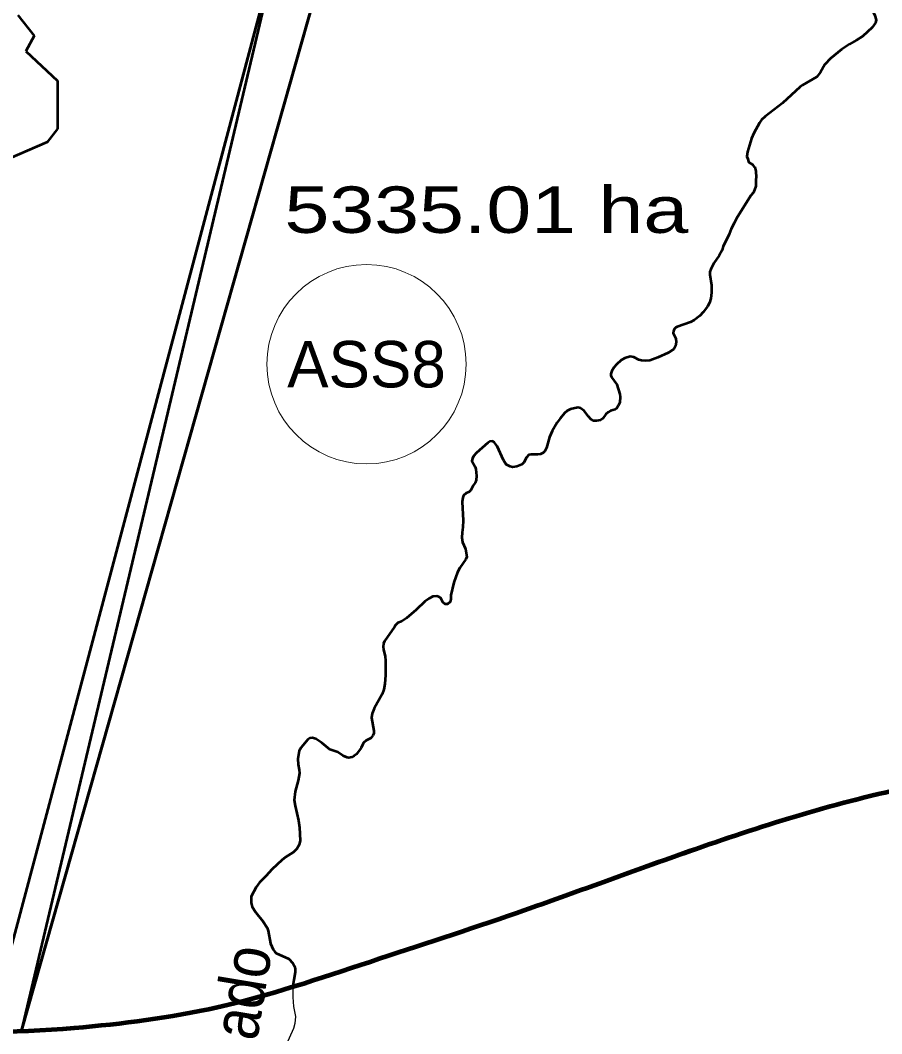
# Model space of a CAD drawing. Extents: x -1643653 to 4543381, y 1624270 to 13878484.
# Drawn here: x 618603 to 627885, y 8953910 to 8964825 of the extents above; entities that cross this region are included whole.
import ezdxf
from ezdxf.enums import TextEntityAlignment as Align

# ---------------------------------------------------------------- set-up
doc = ezdxf.new("R2010")
doc.units = 0
doc.header["$LTSCALE"] = 200
doc.linetypes.add('MEDIUM_DASHED', pattern=[4.5, 3, -1.5])
for name, color, linetype, lineweight in [('1', 7, 'Continuous', 13), ('24', 7, 'Continuous', 25), ('26', 7, 'Continuous', 106), ('27', 7, 'Continuous', 53), ('28', 7, 'Continuous', 53), ('29', 7, 'Continuous', 13), ('45', 7, 'Continuous', 13)]:
    doc.layers.add(name, color=color, linetype=linetype, lineweight=lineweight)
doc.layers.add('49', color=7, linetype='Continuous')
doc.layers.add('63', color=7, linetype='Continuous')

msp = doc.modelspace()

# ---------------------------------------------------------------- linework, layer by layer
at = {"layer": '1', "lineweight": 25}
msp.add_spline([(814781, 9009175.5), (814787.2, 9009173.4), (814796.9, 9009173.4), (814799.4, 9009172.4), (814805.1, 9009174.5), (814805.6, 9009176.5), (814811.7, 9009179.5), (814811.7, 9009179.5), (814801.5, 9009181), (814790.7, 9009181.5), (814784.1, 9009183.1), (814777.4, 9009185.1), (814778.4, 9009175.5)], degree=3, dxfattribs=at)
at = {"layer": '24'}
for points in [[(627864.4, 8965796.7), (627870.8, 8965773.8), (627867.2, 8965732.7), (627839, 8965684.6), (627827.1, 8965654.5), (627811.8, 8965541.3), (627811.5, 8965505.3), (627817.4, 8965449.2), (627838.1, 8965372.1), (627841, 8965321), (627826.7, 8965271.9), (627798.1, 8965236.8), (627783.4, 8965207.8), (627766.8, 8965123.6), (627733.2, 8965082.5), (627726.4, 8965067.5), (627723.3, 8965046.4), (627728.3, 8965015.4), (627739.7, 8964986.4), (627792.5, 8964916.3), (627811.7, 8964876.3), (627823.6, 8964830.2), (627816, 8964796.2)], [(627816, 8964796.2), (627816, 8964796.2), (627780.2, 8964746.1), (627680.5, 8964655.8), (627612, 8964609.6), (627536.8, 8964566.4), (627449.5, 8964509.2), (627333.7, 8964414.8), (627272.4, 8964348.6), (627225, 8964267.4), (627185.5, 8964217.3), (627032.1, 8964127.9), (627004.7, 8964107.8), (626815.8, 8963934.3), (626629.8, 8963789.7), (626590.1, 8963751.6), (626566.7, 8963720.5), (626506, 8963608.3), (626480.1, 8963551.1), (626439.9, 8963406.8), (626430.6, 8963358.8), (626441.2, 8963331.8), (626448.8, 8963299.7), (626457.1, 8963293.7), (626491.3, 8963272.5), (626505.7, 8963251), (626515.9, 8963242.8), (626529.7, 8963201.7), (626531.3, 8963131.3), (626529.2, 8963109.8), (626529.5, 8963038.6), (626501.7, 8962971.9), (626473.9, 8962938.6), (626318.3, 8962688.6), (626296, 8962638.6), (626262.7, 8962577.5), (626240.4, 8962522), (626212.7, 8962460.8), (626174.8, 8962393.8), (626164.1, 8962350.8), (626134.9, 8962291.6), (626076.5, 8962209.4), (626043, 8962145.2), (626033.4, 8962116.2), (626031, 8962086.1), (626050.8, 8961971), (626052.2, 8961893.9), (626043.5, 8961829.8), (626030, 8961782.7), (626007.6, 8961741.6), (625960.4, 8961681.4), (625923.5, 8961643.3), (625862.9, 8961595.1), (625822.7, 8961574), (625681.1, 8961524.7), (625666.2, 8961515.7), (625650, 8961497.6), (625640, 8961477.6), (625636.3, 8961455.5), (625664.5, 8961397.5), (625669.9, 8961359.4), (625663.1, 8961316.3), (625644, 8961283.3), (625582.5, 8961243.1), (625473.5, 8961191.8)], [(625473.5, 8961191.8), (625385.3, 8961162.7), (625335.4, 8961158.6), (625297, 8961160.5), (625268.2, 8961168.5), (625214.1, 8961198.5), (625173.4, 8961205.4), (625117.9, 8961186.3), (625078.9, 8961163.2), (625027.5, 8961119), (625000.9, 8961089), (624975.3, 8961048.8), (624966.1, 8961016.8), (624966.2, 8960999.8), (624973, 8960982.7), (625029.9, 8960900.7), (625064.6, 8960798.6), (625067, 8960768.6), (625061.1, 8960709.5), (625046, 8960671.4), (625027.5, 8960644.3), (625011.3, 8960634.2), (624961, 8960619.2), (624936.3, 8960606.1), (624912, 8960582), (624879.5, 8960536.9), (624854.3, 8960516.8), (624811.3, 8960509.7), (624784.5, 8960512.7), (624750.7, 8960527.7), (624725.6, 8960556.7), (624680, 8960618.7), (624640.1, 8960648.7), (624615.7, 8960653.7), (624577.3, 8960648.6), (624531.2, 8960635.5), (624496.8, 8960619.4)], [(624496.8, 8960619.4), (624466.5, 8960595.3), (624466.5, 8960595.3), (624418.2, 8960536.2), (624388.4, 8960493.1), (624334.1, 8960398.8), (624304.9, 8960334.7), (624271.6, 8960219.4), (624255.9, 8960184.4), (624237, 8960167.3), (624209.4, 8960152.2), (624177.8, 8960149.2), (624105.6, 8960150.1), (624084, 8960144), (624056.4, 8960117.9), (624029.7, 8960062.8), (624008.5, 8960040.7), (623952.6, 8960017.6), (623906.6, 8960011.5), (623879.7, 8960018.5), (623839.9, 8960041.5), (623809.1, 8960087.5), (623742.1, 8960236.6), (623708.6, 8960280.6), (623691, 8960291.6), (623663.5, 8960287.6), (623642.3, 8960274.5), (623518.1, 8960166.2), (623487.9, 8960132.1), (623473.9, 8960107), (623469.3, 8960080), (623503, 8960016.9), (623511.8, 8959991.9), (623518.8, 8959918.8), (623515.2, 8959871.7), (623503, 8959841.6), (623483.8, 8959814.6), (623458.3, 8959764.4), (623435.3, 8959743.4), (623405.8, 8959733.3), (623380.1, 8959708.2), (623370, 8959684.2), (623363, 8959639.1), (623374, 8959437.8), (623371.3, 8959365.7), (623362.7, 8959309.6), (623359.5, 8959254.5), (623367, 8959203.4), (623399.7, 8959131.4), (623414.8, 8959045.2), (623404.2, 8959022.2), (623338.3, 8958926.9), (623315, 8958880.8), (623272.9, 8958769.6), (623243.1, 8958633.3), (623241.6, 8958590.3), (623234, 8958561.2), (623207.1, 8958537.1), (623180.9, 8958538.1), (623154, 8958559.1), (623142.4, 8958588.1), (623129.2, 8958606.1), (623114.3, 8958616.1), (623091.3, 8958624.1), (623048.1, 8958618)], [(623048.1, 8958618), (623008.6, 8958598.9), (622961, 8958563.8), (622867, 8958474.5), (622765.3, 8958385.2), (622710.3, 8958350.1), (622672.6, 8958336), (622645.8, 8958310.9), (622635.8, 8958292.8), (622526.4, 8958139.4), (622516.5, 8958114.4), (622511.7, 8958078.3), (622515.3, 8958048.3), (622533.3, 8957971.2), (622537.7, 8957930.1), (622539.2, 8957771.9), (622532.6, 8957678.7), (622519.6, 8957617.6), (622503, 8957566.5), (622414.7, 8957413.1), (622392.8, 8957358), (622387.2, 8957313.9), (622413.1, 8957173.7), (622412, 8957144.7), (622401.3, 8957121.6), (622379.3, 8957091.6), (622329.5, 8957067.4), (622303.6, 8957046.4), (622292.3, 8957028.3), (622277.2, 8956988.2), (622224.7, 8956922.1), (622199.4, 8956902), (622173.6, 8956888.9), (622144.5, 8956882.9), (622124.1, 8956884.8), (622082.2, 8956903.8), (622023.4, 8956940.8)], [(622023.4, 8956940.8), (621940, 8956970.7), (621852.9, 8957044.7), (621852.9, 8957044.7), (621788.3, 8957084.6), (621747.1, 8957098.6), (621722, 8957094.5), (621699.9, 8957079.5), (621630.5, 8956993.2), (621609.1, 8956955.1), (621593, 8956869), (621597.7, 8956809.9), (621609.5, 8956752.8), (621610.3, 8956716.8), (621596.7, 8956635.6), (621564.2, 8956517.4), (621555.7, 8956425.2), (621563.4, 8956363.1), (621602.1, 8956205), (621612.3, 8956132.8), (621617.2, 8955989.6), (621609.4, 8955942.6), (621581.9, 8955900.4), (621546.5, 8955864.3), (621462.3, 8955810.1), (621421.6, 8955778), (621315.5, 8955681.7), (621248.5, 8955606.5), (621180.3, 8955539.2), (621144.2, 8955490.1), (621090.8, 8955387.9), (621089.6, 8955318.8), (621102.6, 8955276.7), (621141.2, 8955216.7), (621216.2, 8955123.7), (621263.9, 8955050.6), (621273.7, 8955018.6), (621298.4, 8954880.4), (621326.6, 8954818.3), (621344.8, 8954792.3), (621361.2, 8954778.3), (621494.9, 8954716.5), (621540.7, 8954668.5), (621556.5, 8954637.4), (621563.9, 8954607.4), (621564.5, 8954574.3), (621548.8, 8954491.2), (621540.9, 8954424.1), (621539.7, 8954301.9), (621548, 8954202.7), (621568.6, 8954096.6), (621562.7, 8954019.5), (621547, 8953964.4), (621433.8, 8953717.8)]]:
    msp.add_lwpolyline(points, dxfattribs=at)
at = {"layer": '26'}
msp.add_spline([(645710.9, 8949471.4), (644721.9, 8950215.5), (643631.5, 8951123.7), (642665.6, 8952010.9), (642072.6, 8952588.9), (640582.3, 8953977.6), (638005.5, 8955508.7), (636255.8, 8956201.4), (634307.9, 8956672.6), (632583.3, 8956799.8), (628516.3, 8956628.1), (626161.4, 8955993.9), (623953.8, 8955209.7), (622371.6, 8954682.1), (620725.9, 8954192.9), (619183.7, 8953970.3), (617209.7, 8953965.7), (615658.4, 8954379), (614681.6, 8955057.1), (613704.6, 8955684.2), (612906.2, 8956374.2), (612068.3, 8956835.4), (609416.9, 8956401.3), (608625.2, 8956035.7), (607870.9, 8955517.4), (607396.1, 8954883.6), (607164, 8954388.6), (606950.6, 8954069.9)], degree=3, dxfattribs=at)
at = {"layer": '27'}
msp.add_line((618614.3, 8953943), (622031.1, 8965989.3), dxfattribs=at)
for points in [[(621430.6, 8965386.2), (622031.1, 8965989.3), (618614.3, 8953943), (618257.6, 8953925.9)], [(627864.4, 8965796.7), (627870.8, 8965773.8), (627867.2, 8965732.7), (627839, 8965684.6), (627827.1, 8965654.5), (627811.8, 8965541.3), (627811.5, 8965505.3), (627817.4, 8965449.2), (627838.1, 8965372.1), (627841, 8965321), (627826.7, 8965271.9), (627798.1, 8965236.8), (627783.4, 8965207.8), (627766.8, 8965123.6), (627733.2, 8965082.5), (627726.4, 8965067.5), (627723.3, 8965046.4), (627728.3, 8965015.4), (627739.7, 8964986.4), (627792.5, 8964916.3), (627811.7, 8964876.3), (627823.6, 8964830.2), (627816, 8964796.2)], [(627864.4, 8965796.7), (627870.8, 8965773.8), (627867.2, 8965732.7), (627839, 8965684.6), (627827.1, 8965654.5), (627811.8, 8965541.3), (627811.5, 8965505.3), (627817.4, 8965449.2), (627838.1, 8965372.1), (627841, 8965321), (627826.7, 8965271.9), (627798.1, 8965236.8), (627783.4, 8965207.8), (627766.8, 8965123.6), (627733.2, 8965082.5), (627726.4, 8965067.5), (627723.3, 8965046.4), (627728.3, 8965015.4), (627739.7, 8964986.4), (627792.5, 8964916.3), (627811.7, 8964876.3), (627823.6, 8964830.2), (627816, 8964796.2)], [(627816, 8964796.2), (627816, 8964796.2), (627780.2, 8964746.1), (627680.5, 8964655.8), (627612, 8964609.6), (627536.8, 8964566.4), (627449.5, 8964509.2), (627333.7, 8964414.8), (627272.4, 8964348.6), (627225, 8964267.4), (627185.5, 8964217.3), (627032.1, 8964127.9), (627004.7, 8964107.8), (626815.8, 8963934.3), (626629.8, 8963789.7), (626590.1, 8963751.6), (626566.7, 8963720.5), (626506, 8963608.3), (626480.1, 8963551.1), (626439.9, 8963406.8), (626430.6, 8963358.8), (626441.2, 8963331.8), (626448.8, 8963299.7), (626457.1, 8963293.7), (626491.3, 8963272.5), (626505.7, 8963251), (626515.9, 8963242.8), (626529.7, 8963201.7), (626531.3, 8963131.3), (626529.2, 8963109.8), (626529.5, 8963038.6), (626501.7, 8962971.9), (626473.9, 8962938.6), (626318.3, 8962688.6), (626296, 8962638.6), (626262.7, 8962577.5), (626240.4, 8962522), (626212.7, 8962460.8), (626174.8, 8962393.8), (626164.1, 8962350.8), (626134.9, 8962291.6), (626076.5, 8962209.4), (626043, 8962145.2), (626033.4, 8962116.2), (626031, 8962086.1), (626050.8, 8961971), (626052.2, 8961893.9), (626043.5, 8961829.8), (626030, 8961782.7), (626007.6, 8961741.6), (625960.4, 8961681.4), (625923.5, 8961643.3), (625862.9, 8961595.1), (625822.7, 8961574), (625681.1, 8961524.7), (625666.2, 8961515.7), (625650, 8961497.6), (625640, 8961477.6), (625636.3, 8961455.5), (625664.5, 8961397.5), (625669.9, 8961359.4), (625663.1, 8961316.3), (625644, 8961283.3), (625582.5, 8961243.1), (625473.5, 8961191.8)], [(627816, 8964796.2), (627816, 8964796.2), (627780.2, 8964746.1), (627680.5, 8964655.8), (627612, 8964609.6), (627536.8, 8964566.4), (627449.5, 8964509.2), (627333.7, 8964414.8), (627272.4, 8964348.6), (627225, 8964267.4), (627185.5, 8964217.3), (627032.1, 8964127.9), (627004.7, 8964107.8), (626815.8, 8963934.3), (626629.8, 8963789.7), (626590.1, 8963751.6), (626566.7, 8963720.5), (626506, 8963608.3), (626480.1, 8963551.1), (626439.9, 8963406.8), (626430.6, 8963358.8), (626441.2, 8963331.8), (626448.8, 8963299.7), (626457.1, 8963293.7), (626491.3, 8963272.5), (626505.7, 8963251), (626515.9, 8963242.8), (626529.7, 8963201.7), (626531.3, 8963131.3), (626529.2, 8963109.8), (626529.5, 8963038.6), (626501.7, 8962971.9), (626473.9, 8962938.6), (626318.3, 8962688.6), (626296, 8962638.6), (626262.7, 8962577.5), (626240.4, 8962522), (626212.7, 8962460.8), (626174.8, 8962393.8), (626164.1, 8962350.8), (626134.9, 8962291.6), (626076.5, 8962209.4), (626043, 8962145.2), (626033.4, 8962116.2), (626031, 8962086.1), (626050.8, 8961971), (626052.2, 8961893.9), (626043.5, 8961829.8), (626030, 8961782.7), (626007.6, 8961741.6), (625960.4, 8961681.4), (625923.5, 8961643.3), (625862.9, 8961595.1), (625822.7, 8961574), (625681.1, 8961524.7), (625666.2, 8961515.7), (625650, 8961497.6), (625640, 8961477.6), (625636.3, 8961455.5), (625664.5, 8961397.5), (625669.9, 8961359.4), (625663.1, 8961316.3), (625644, 8961283.3), (625582.5, 8961243.1), (625473.5, 8961191.8)], [(625473.5, 8961191.8), (625385.3, 8961162.7), (625335.4, 8961158.6), (625297, 8961160.5), (625268.2, 8961168.5), (625214.1, 8961198.5), (625173.4, 8961205.4), (625117.9, 8961186.3), (625078.9, 8961163.2), (625027.5, 8961119), (625000.9, 8961089), (624975.3, 8961048.8), (624966.1, 8961016.8), (624966.2, 8960999.8), (624973, 8960982.7), (625029.9, 8960900.7), (625064.6, 8960798.6), (625067, 8960768.6), (625061.1, 8960709.5), (625046, 8960671.4), (625027.5, 8960644.3), (625011.3, 8960634.2), (624961, 8960619.2), (624936.3, 8960606.1), (624912, 8960582), (624879.5, 8960536.9), (624854.3, 8960516.8), (624811.3, 8960509.7), (624784.5, 8960512.7), (624750.7, 8960527.7), (624725.6, 8960556.7), (624680, 8960618.7), (624640.1, 8960648.7), (624615.7, 8960653.7), (624577.3, 8960648.6), (624531.2, 8960635.5), (624496.8, 8960619.4)], [(625473.5, 8961191.8), (625385.3, 8961162.7), (625335.4, 8961158.6), (625297, 8961160.5), (625268.2, 8961168.5), (625214.1, 8961198.5), (625173.4, 8961205.4), (625117.9, 8961186.3), (625078.9, 8961163.2), (625027.5, 8961119), (625000.9, 8961089), (624975.3, 8961048.8), (624966.1, 8961016.8), (624966.2, 8960999.8), (624973, 8960982.7), (625029.9, 8960900.7), (625064.6, 8960798.6), (625067, 8960768.6), (625061.1, 8960709.5), (625046, 8960671.4), (625027.5, 8960644.3), (625011.3, 8960634.2), (624961, 8960619.2), (624936.3, 8960606.1), (624912, 8960582), (624879.5, 8960536.9), (624854.3, 8960516.8), (624811.3, 8960509.7), (624784.5, 8960512.7), (624750.7, 8960527.7), (624725.6, 8960556.7), (624680, 8960618.7), (624640.1, 8960648.7), (624615.7, 8960653.7), (624577.3, 8960648.6), (624531.2, 8960635.5), (624496.8, 8960619.4)], [(624496.8, 8960619.4), (624466.5, 8960595.3), (624466.5, 8960595.3), (624418.2, 8960536.2), (624388.4, 8960493.1), (624334.1, 8960398.8), (624304.9, 8960334.7), (624271.6, 8960219.4), (624255.9, 8960184.4), (624237, 8960167.3), (624209.4, 8960152.2), (624177.8, 8960149.2), (624105.6, 8960150.1), (624084, 8960144), (624056.4, 8960117.9), (624029.7, 8960062.8), (624008.5, 8960040.7), (623952.6, 8960017.6), (623906.6, 8960011.5), (623879.7, 8960018.5), (623839.9, 8960041.5), (623809.1, 8960087.5), (623742.1, 8960236.6), (623708.6, 8960280.6), (623691, 8960291.6), (623663.5, 8960287.6), (623642.3, 8960274.5), (623518.1, 8960166.2), (623487.9, 8960132.1), (623473.9, 8960107), (623469.3, 8960080), (623503, 8960016.9), (623511.8, 8959991.9), (623518.8, 8959918.8), (623515.2, 8959871.7), (623503, 8959841.6), (623483.8, 8959814.6), (623458.3, 8959764.4), (623435.3, 8959743.4), (623405.8, 8959733.3), (623380.1, 8959708.2), (623370, 8959684.2), (623363, 8959639.1), (623374, 8959437.8), (623371.3, 8959365.7), (623362.7, 8959309.6), (623359.5, 8959254.5), (623367, 8959203.4), (623399.7, 8959131.4), (623414.8, 8959045.2), (623404.2, 8959022.2), (623338.3, 8958926.9), (623315, 8958880.8), (623272.9, 8958769.6), (623243.1, 8958633.3), (623241.6, 8958590.3), (623234, 8958561.2), (623207.1, 8958537.1), (623180.9, 8958538.1), (623154, 8958559.1), (623142.4, 8958588.1), (623129.2, 8958606.1), (623114.3, 8958616.1), (623091.3, 8958624.1), (623048.1, 8958618)], [(624496.8, 8960619.4), (624466.5, 8960595.3), (624466.5, 8960595.3), (624418.2, 8960536.2), (624388.4, 8960493.1), (624334.1, 8960398.8), (624304.9, 8960334.7), (624271.6, 8960219.4), (624255.9, 8960184.4), (624237, 8960167.3), (624209.4, 8960152.2), (624177.8, 8960149.2), (624105.6, 8960150.1), (624084, 8960144), (624056.4, 8960117.9), (624029.7, 8960062.8), (624008.5, 8960040.7), (623952.6, 8960017.6), (623906.6, 8960011.5), (623879.7, 8960018.5), (623839.9, 8960041.5), (623809.1, 8960087.5), (623742.1, 8960236.6), (623708.6, 8960280.6), (623691, 8960291.6), (623663.5, 8960287.6), (623642.3, 8960274.5), (623518.1, 8960166.2), (623487.9, 8960132.1), (623473.9, 8960107), (623469.3, 8960080), (623503, 8960016.9), (623511.8, 8959991.9), (623518.8, 8959918.8), (623515.2, 8959871.7), (623503, 8959841.6), (623483.8, 8959814.6), (623458.3, 8959764.4), (623435.3, 8959743.4), (623405.8, 8959733.3), (623380.1, 8959708.2), (623370, 8959684.2), (623363, 8959639.1), (623374, 8959437.8), (623371.3, 8959365.7), (623362.7, 8959309.6), (623359.5, 8959254.5), (623367, 8959203.4), (623399.7, 8959131.4), (623414.8, 8959045.2), (623404.2, 8959022.2), (623338.3, 8958926.9), (623315, 8958880.8), (623272.9, 8958769.6), (623243.1, 8958633.3), (623241.6, 8958590.3), (623234, 8958561.2), (623207.1, 8958537.1), (623180.9, 8958538.1), (623154, 8958559.1), (623142.4, 8958588.1), (623129.2, 8958606.1), (623114.3, 8958616.1), (623091.3, 8958624.1), (623048.1, 8958618)], [(623048.1, 8958618), (623008.6, 8958598.9), (622961, 8958563.8), (622867, 8958474.5), (622765.3, 8958385.2), (622710.3, 8958350.1), (622672.6, 8958336), (622645.8, 8958310.9), (622635.8, 8958292.8), (622526.4, 8958139.4), (622516.5, 8958114.4), (622511.7, 8958078.3), (622515.3, 8958048.3), (622533.3, 8957971.2), (622537.7, 8957930.1), (622539.2, 8957771.9), (622532.6, 8957678.7), (622519.6, 8957617.6), (622503, 8957566.5), (622414.7, 8957413.1), (622392.8, 8957358), (622387.2, 8957313.9), (622413.1, 8957173.7), (622412, 8957144.7), (622401.3, 8957121.6), (622379.3, 8957091.6), (622329.5, 8957067.4), (622303.6, 8957046.4), (622292.3, 8957028.3), (622277.2, 8956988.2), (622224.7, 8956922.1), (622199.4, 8956902), (622173.6, 8956888.9), (622144.5, 8956882.9), (622124.1, 8956884.8), (622082.2, 8956903.8), (622023.4, 8956940.8)], [(623048.1, 8958618), (623008.6, 8958598.9), (622961, 8958563.8), (622867, 8958474.5), (622765.3, 8958385.2), (622710.3, 8958350.1), (622672.6, 8958336), (622645.8, 8958310.9), (622635.8, 8958292.8), (622526.4, 8958139.4), (622516.5, 8958114.4), (622511.7, 8958078.3), (622515.3, 8958048.3), (622533.3, 8957971.2), (622537.7, 8957930.1), (622539.2, 8957771.9), (622532.6, 8957678.7), (622519.6, 8957617.6), (622503, 8957566.5), (622414.7, 8957413.1), (622392.8, 8957358), (622387.2, 8957313.9), (622413.1, 8957173.7), (622412, 8957144.7), (622401.3, 8957121.6), (622379.3, 8957091.6), (622329.5, 8957067.4), (622303.6, 8957046.4), (622292.3, 8957028.3), (622277.2, 8956988.2), (622224.7, 8956922.1), (622199.4, 8956902), (622173.6, 8956888.9), (622144.5, 8956882.9), (622124.1, 8956884.8), (622082.2, 8956903.8), (622023.4, 8956940.8)], [(622023.4, 8956940.8), (621940, 8956970.7), (621852.9, 8957044.7), (621852.9, 8957044.7), (621788.3, 8957084.6), (621747.1, 8957098.6), (621722, 8957094.5), (621699.9, 8957079.5), (621630.5, 8956993.2), (621609.1, 8956955.1), (621593, 8956869), (621597.7, 8956809.9), (621609.5, 8956752.8), (621610.3, 8956716.8), (621596.7, 8956635.6), (621564.2, 8956517.4), (621555.7, 8956425.2), (621563.4, 8956363.1), (621602.1, 8956205), (621612.3, 8956132.8), (621617.2, 8955989.6), (621609.4, 8955942.6), (621581.9, 8955900.4), (621546.5, 8955864.3), (621462.3, 8955810.1), (621421.6, 8955778), (621315.5, 8955681.7), (621248.5, 8955606.5), (621180.3, 8955539.2), (621144.2, 8955490.1), (621090.8, 8955387.9), (621089.6, 8955318.8), (621102.6, 8955276.7), (621141.2, 8955216.7), (621216.2, 8955123.7), (621263.9, 8955050.6), (621273.7, 8955018.6), (621298.4, 8954880.4), (621326.6, 8954818.3), (621344.8, 8954792.3), (621361.2, 8954778.3), (621494.9, 8954716.5), (621540.7, 8954668.5), (621556.5, 8954637.4), (621563.9, 8954607.4), (621564.5, 8954574.3), (621548.8, 8954491.2), (621540.9, 8954424.1), (621540.8, 8954419.8)], [(622023.4, 8956940.8), (621940, 8956970.7), (621852.9, 8957044.7), (621852.9, 8957044.7), (621788.3, 8957084.6), (621747.1, 8957098.6), (621722, 8957094.5), (621699.9, 8957079.5), (621630.5, 8956993.2), (621609.1, 8956955.1), (621593, 8956869), (621597.7, 8956809.9), (621609.5, 8956752.8), (621610.3, 8956716.8), (621596.7, 8956635.6), (621564.2, 8956517.4), (621555.7, 8956425.2), (621563.4, 8956363.1), (621602.1, 8956205), (621612.3, 8956132.8), (621617.2, 8955989.6), (621609.4, 8955942.6), (621581.9, 8955900.4), (621546.5, 8955864.3), (621462.3, 8955810.1), (621421.6, 8955778), (621315.5, 8955681.7), (621248.5, 8955606.5), (621180.3, 8955539.2), (621144.2, 8955490.1), (621090.8, 8955387.9), (621089.6, 8955318.8), (621102.6, 8955276.7), (621141.2, 8955216.7), (621216.2, 8955123.7), (621263.9, 8955050.6), (621273.7, 8955018.6), (621298.4, 8954880.4), (621326.6, 8954818.3), (621344.8, 8954792.3), (621361.2, 8954778.3), (621494.9, 8954716.5), (621540.7, 8954668.5), (621556.5, 8954637.4), (621563.9, 8954607.4), (621564.5, 8954574.3), (621548.8, 8954491.2), (621540.9, 8954424.1), (621540.8, 8954419.8)]]:
    msp.add_lwpolyline(points, dxfattribs=at)
at = {"layer": '27', "linetype": 'MEDIUM_DASHED'}
msp.add_lwpolyline([(618576.8, 8964881.8), (618751.3, 8964656.1), (618661.9, 8964494.3), (619002.3, 8964172.9), (619002.3, 8963657.7), (618891.7, 8963513), (618376.5, 8963291.4)], dxfattribs=at)
at = {"layer": '27'}
for points in [[(621540.8, 8954419.8), (622371.6, 8954682.1), (623953.8, 8955209.7), (626795.7, 8956205.5), (628223, 8956576.8), (628372, 8956602)], [(621540.8, 8954419.8), (620725.9, 8954192.9), (619183.7, 8953970.3), (618614.3, 8953943)]]:
    msp.add_spline(points, degree=3, dxfattribs=at)
at = {"layer": '28'}
msp.add_line((621434.1, 8965861.3), (618611.5, 8953933.2), dxfattribs=at)
for points in [[(620631.9, 8965673.6), (621434.1, 8965861.3), (618611.5, 8953933.2), (618257.6, 8953925.9)], [(620631.9, 8965673.6), (621434.1, 8965861.3), (618257.6, 8953925.9), (618257.6, 8953925.9)]]:
    msp.add_lwpolyline(points, dxfattribs=at)
for points in [[(618257.6, 8953925.9), (619183.7, 8953970.3), (620725.9, 8954192.9), (622371.6, 8954682.1), (623953.8, 8955209.7), (626795.7, 8956205.5), (628223, 8956576.8), (631243.2, 8956803.3), (633721.3, 8956728), (636313.6, 8956183.1), (638079.6, 8955470.7), (639993.2, 8954394), (641326.9, 8953340.4), (642237.8, 8952425.4), (643343.9, 8951370.7), (644721.9, 8950215.5), (645793.1, 8949290.9)], [(618257.6, 8953925.9), (619183.7, 8953970.3), (620725.9, 8954192.9), (622371.6, 8954682.1), (623953.8, 8955209.7), (626185.5, 8955995.2), (628043.5, 8956541.4), (631351.2, 8956802.4), (633709.5, 8956728.8), (635993.8, 8956280.5), (637686.3, 8955648.2), (639291.4, 8954828.8), (640588.9, 8953973.3), (641709, 8952948.6), (643376.9, 8951340.4), (644721.9, 8950215.5), (645793.1, 8949290.9)]]:
    msp.add_spline(points, degree=3, dxfattribs=at)
at = {"layer": '29', "lineweight": 53}
msp.add_line((621434.1, 8965861.3), (618257.6, 8953925.9), dxfattribs=at)
at = {"layer": '45'}
msp.add_circle((622333.4, 8961121.3), 1073.6, dxfattribs=at)

# ---------------------------------------------------------------- texts
msp.add_text('ASS8', height=500, dxfattribs=at).set_placement((622333.4, 8960871.3), align=Align.CENTER)
at = {"layer": '49', "width": 0.9}
msp.add_text('Rio Talhado', height=500, rotation=80.538, dxfattribs=at).set_placement((621050.4, 8953212.3), align=Align.CENTER)
at = {"layer": '63', "width": 1.3}
msp.add_text(' 5335.01 ha', height=500, dxfattribs=at).set_placement((621208, 8962535.3))

doc.saveas('drawing.dxf')
